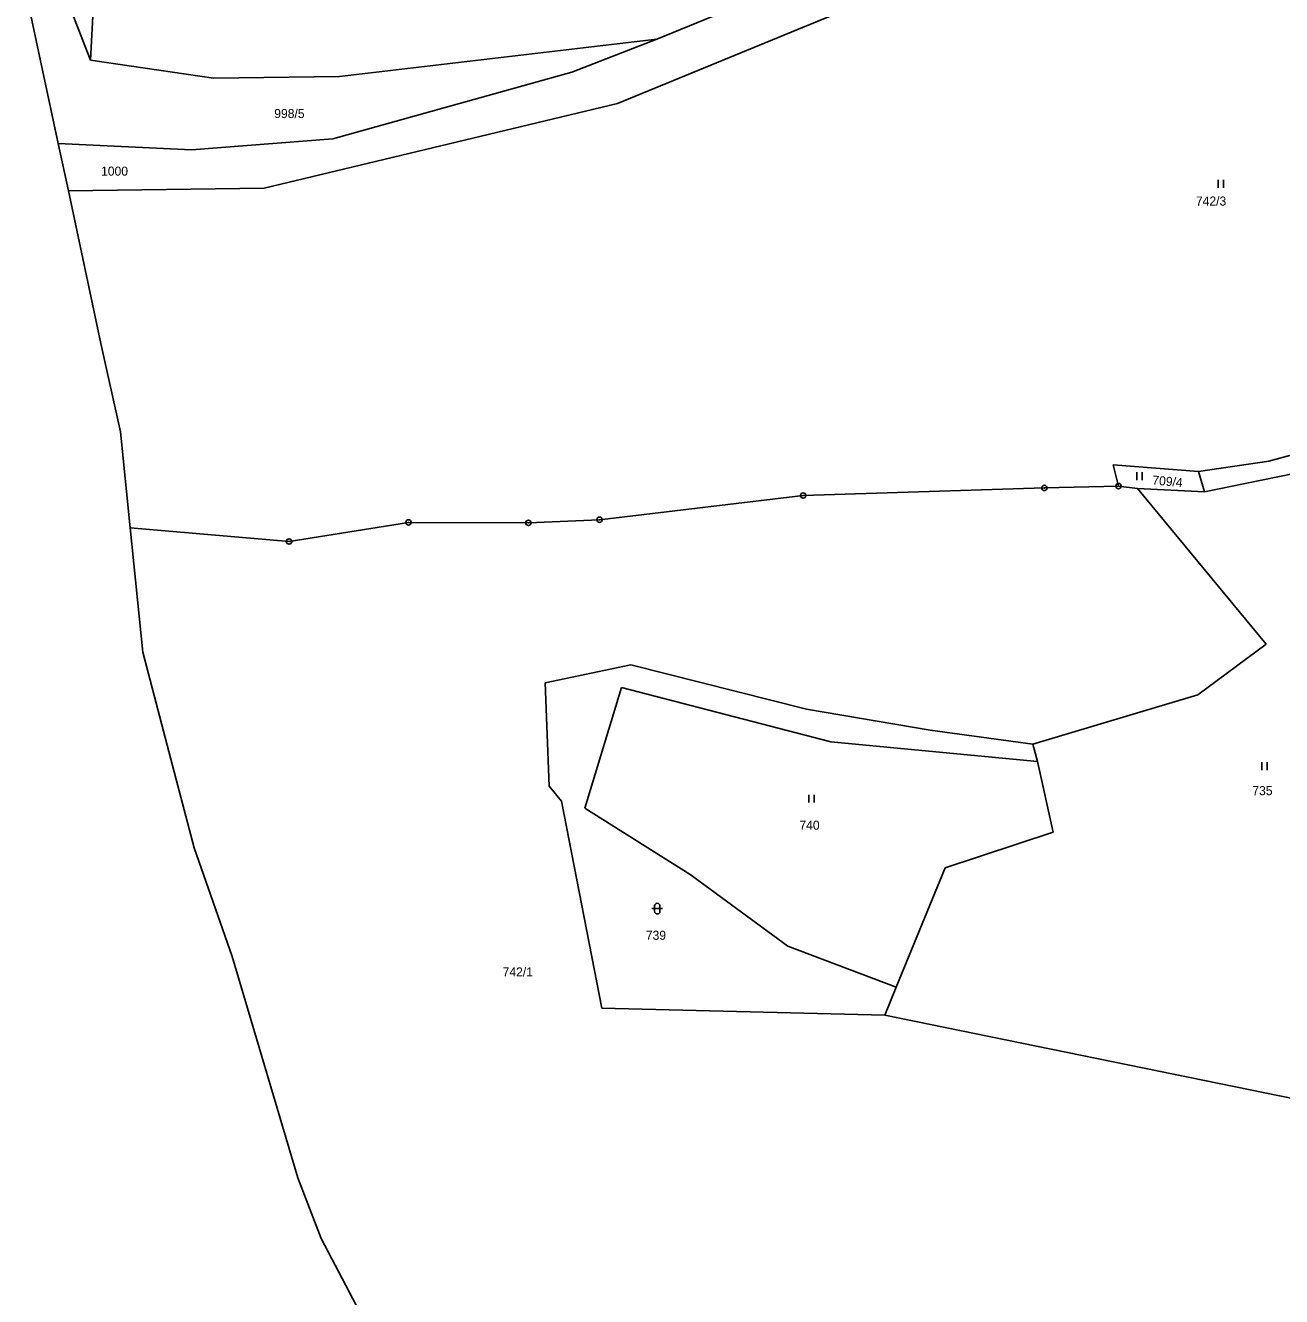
# Model space of a CAD drawing. Extents: x -754970 to -752637, y -970569 to -968179.
# Drawn here: x -754628.3 to -754392.6, y -969916.8 to -969678.2 of the extents above; entities that cross this region are included whole.
import ezdxf
from ezdxf.enums import TextEntityAlignment as Align

# ---------------------------------------------------------------- set-up
doc = ezdxf.new("R2010")
doc.units = 0
doc.header["$LTSCALE"] = 0.68
for name, color, linetype, lineweight in [('1', 7, 'Continuous', 25), ('3', 7, 'Continuous', 25), ('8', 7, 'Continuous', 25)]:
    doc.layers.add(name, color=color, linetype=linetype, lineweight=lineweight)
doc.layers.add('2', color=7, linetype='Continuous')

msp = doc.modelspace()

# ---------------------------------------------------------------- linework, layer by layer
at = {"layer": '1'}
for p, q in [((-754473.16, -969665.8), (-754509.76, -969680.77)), ((-754621.81, -969669.94), (-754616.05, -969684.73)), ((-754628.26, -969671.46), (-754622.1, -969700.37)), ((-754616.05, -969684.73), (-754615.48, -969674.12)), ((-754517.2, -969692.86), (-754468.35, -969672.78)), ((-754509.76, -969680.77), (-754569.35, -969687.78)), ((-754525.72, -969686.98), (-754509.76, -969680.77)), ((-754616.05, -969684.73), (-754592.95, -969688.13)), ((-754592.95, -969688.13), (-754569.35, -969687.78)), ((-754570.59, -969699.49), (-754525.72, -969686.98)), ((-754583.47, -969708.77), (-754517.2, -969692.86)), ((-754622.1, -969700.37), (-754597.1, -969701.57)), ((-754620.2, -969709.26), (-754622.1, -969700.37)), ((-754597.1, -969701.57), (-754570.59, -969699.49)), ((-754620.2, -969709.26), (-754583.47, -969708.77)), ((-754620.2, -969709.26), (-754614.1, -969737.9)), ((-754610.41, -969754.46), (-754614.1, -969737.9)), ((-754353.51, -969748.57), (-754394.94, -969759.98)), ((-754610.41, -969754.46), (-754608.59, -969772.51)), ((-754394.94, -969759.98), (-754408.15, -969761.92)), ((-754399.09, -969764.13), (-754380.69, -969760.33)), ((-754423.16, -969764.66), (-754424.15, -969760.7)), ((-754408.15, -969761.92), (-754424.15, -969760.7)), ((-754407.04, -969765.73), (-754408.15, -969761.92)), ((-754482.34, -969766.43), (-754437.07, -969765)), ((-754423.16, -969764.66), (-754437.07, -969765)), ((-754423.16, -969764.66), (-754419.61, -969765.1)), ((-754419.61, -969765.1), (-754407.04, -969765.73)), ((-754419.61, -969765.1), (-754395.48, -969794.33)), ((-754407.04, -969765.73), (-754399.09, -969764.13)), ((-754520.54, -969770.97), (-754482.34, -969766.43)), ((-754608.59, -969772.51), (-754606.24, -969795.85)), ((-754608.59, -969772.51), (-754578.79, -969775.06)), ((-754578.79, -969775.06), (-754556.38, -969771.47)), ((-754556.38, -969771.47), (-754533.89, -969771.56)), ((-754533.89, -969771.56), (-754520.54, -969770.97)), ((-754600.98, -969815.93), (-754606.24, -969795.85)), ((-754408.27, -969803.85), (-754395.48, -969794.33)), ((-754514.66, -969798.23), (-754530.71, -969801.58)), ((-754481.68, -969806.55), (-754514.66, -969798.23)), ((-754530.71, -969801.58), (-754529.98, -969821)), ((-754523.27, -969825.09), (-754516.41, -969802.46)), ((-754516.41, -969802.46), (-754477.16, -969812.68)), ((-754439.23, -969813.11), (-754408.27, -969803.85)), ((-754458.49, -969810.49), (-754481.68, -969806.55)), ((-754439.23, -969813.11), (-754458.49, -969810.49)), ((-754438.35, -969816.33), (-754477.16, -969812.68)), ((-754438.35, -969816.33), (-754439.23, -969813.11)), ((-754596.63, -969832.54), (-754600.98, -969815.93)), ((-754435.43, -969829.61), (-754438.35, -969816.33)), ((-754529.98, -969821), (-754527.68, -969823.77)), ((-754527.68, -969823.77), (-754520.14, -969862.61)), ((-754503.56, -969837.55), (-754523.27, -969825.09)), ((-754455.71, -969836.32), (-754435.43, -969829.61)), ((-754589.48, -969852.95), (-754596.63, -969832.54)), ((-754455.71, -969836.32), (-754464.87, -969858.72)), ((-754485.22, -969851.03), (-754503.56, -969837.55)), ((-754464.87, -969858.72), (-754485.22, -969851.03)), ((-754577.14, -969894.47), (-754589.48, -969852.95)), ((-754464.87, -969858.72), (-754467.01, -969863.95)), ((-754520.14, -969862.61), (-754467.01, -969863.95)), ((-754467.01, -969863.95), (-754372.96, -969883.19)), ((-754572.75, -969905.84), (-754577.14, -969894.47)), ((-754572.75, -969905.84), (-754562.12, -969926.14))]:
    msp.add_line(p, q, dxfattribs=at)
at = {"layer": '3'}
for p, q in [((-754404.481, -969708.67), (-754404.481, -969707.17)), ((-754403.48, -969708.67), (-754403.48, -969707.17)), ((-754419.721, -969763.56), (-754419.721, -969762.06)), ((-754418.72, -969763.56), (-754418.72, -969762.06)), ((-754396.271, -969818), (-754396.271, -969816.5)), ((-754395.27, -969818), (-754395.27, -969816.5)), ((-754481.241, -969824.07), (-754481.241, -969822.57)), ((-754480.24, -969824.07), (-754480.24, -969822.57)), ((-754510.701, -969843.961), (-754508.699, -969843.961)), ((-754510.201, -969843.461), (-754510.201, -969844.462)), ((-754509.199, -969844.462), (-754509.199, -969843.461))]:
    msp.add_line(p, q, dxfattribs=at)
for centre, start, end in [((-754509.7, -969843.4609), 0, 180), ((-754509.7, -969844.4609), 180, 359.98789)]:
    msp.add_arc(centre, 0.5, start, end, dxfattribs=at)
at = {"layer": '8'}
for centre, radius in [((-754437.07, -969764.9999), 0.5), ((-754437.07, -969764.9999), 0.0303), ((-754423.16, -969764.6599), 0.5), ((-754423.16, -969764.6599), 0.0303), ((-754482.34, -969766.4299), 0.5), ((-754482.34, -969766.4299), 0.0303), ((-754556.38, -969771.4699), 0.5), ((-754556.38, -969771.4699), 0.0303), ((-754533.89, -969771.5599), 0.5), ((-754533.89, -969771.5599), 0.0303), ((-754520.54, -969770.9699), 0.5), ((-754520.54, -969770.9699), 0.0303), ((-754578.79, -969775.0599), 0.5), ((-754578.79, -969775.0599), 0.0303)]:
    msp.add_circle(centre, radius, dxfattribs=at)

# ---------------------------------------------------------------- texts
at = {"layer": '2'}
for s, p in [('998/5', (-754578.73, -969695.595)), ('1000', (-754611.54, -969706.405)), ('742/3', (-754405.8, -969712.015)), ('735', (-754396.159, -969822.665)), ('740', (-754481.139, -969829.145)), ('739', (-754509.959, -969849.805)), ('742/1', (-754535.88, -969856.685))]:
    msp.add_text(s, height=1.7, dxfattribs=at).set_placement(p, align=Align.CENTER)
msp.add_text('709/4', height=1.7, rotation=355, dxfattribs=at).set_placement((-754414.0391, -969764.6065), align=Align.CENTER)

doc.saveas('drawing.dxf')
